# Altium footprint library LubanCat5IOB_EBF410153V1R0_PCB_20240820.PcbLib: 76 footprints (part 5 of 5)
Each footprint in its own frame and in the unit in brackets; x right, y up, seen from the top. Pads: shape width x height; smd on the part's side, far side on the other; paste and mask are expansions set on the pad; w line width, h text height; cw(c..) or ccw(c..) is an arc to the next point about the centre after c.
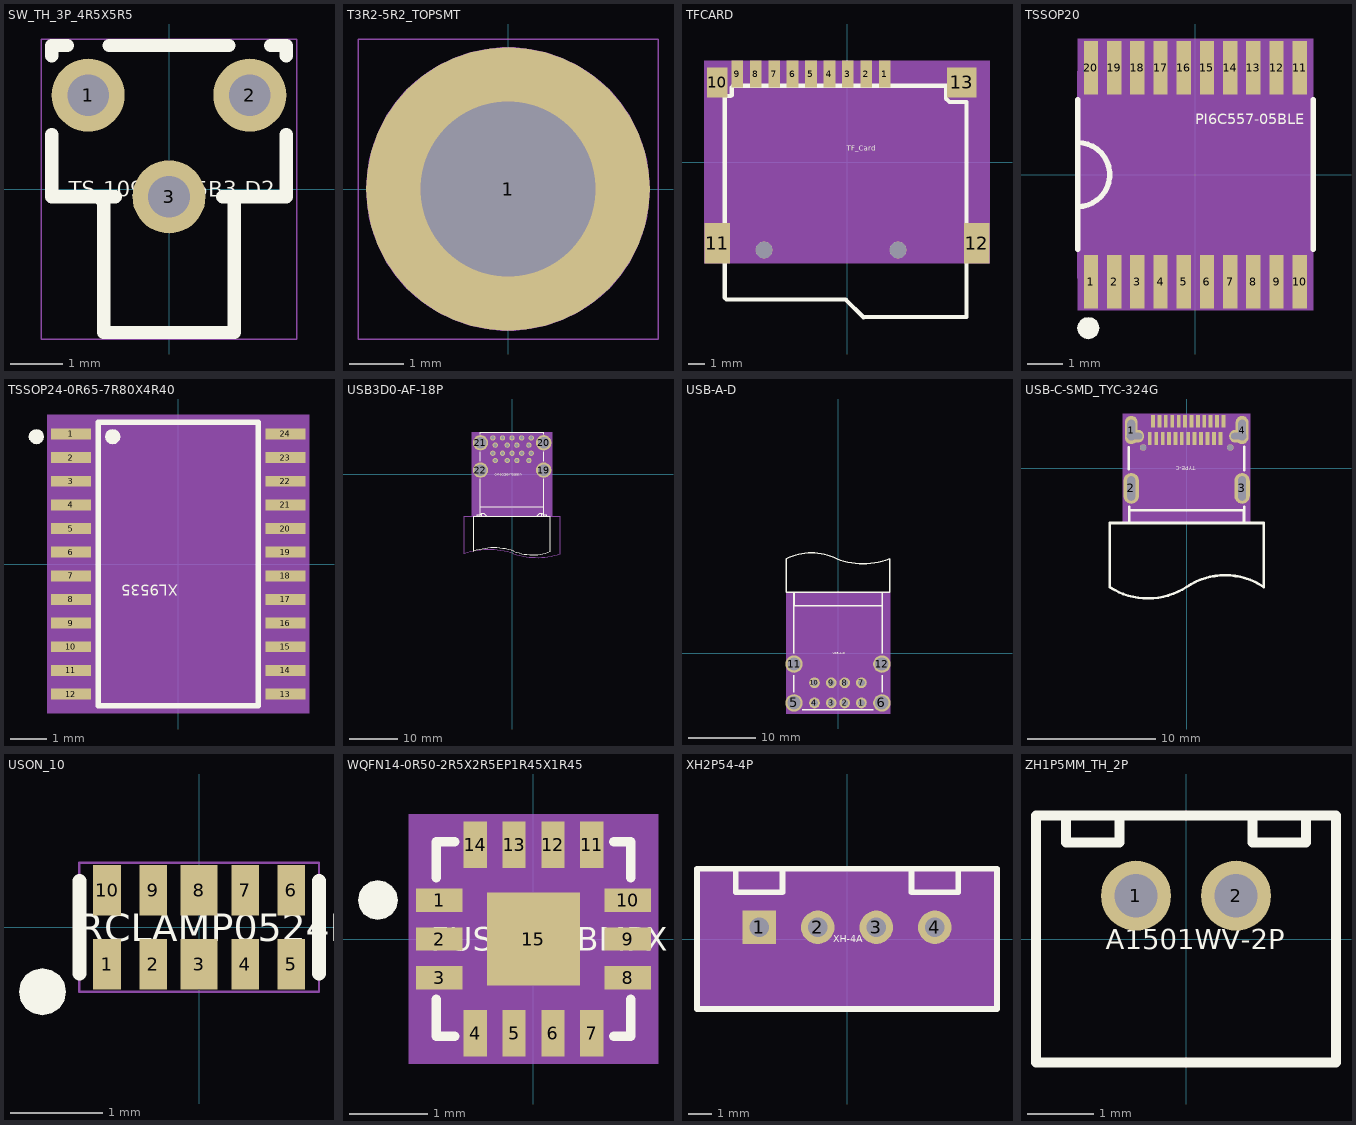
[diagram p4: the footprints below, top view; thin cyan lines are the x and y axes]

## SW_TH_3P_4R5X5R5 [mm] "SW_TH_3P_4R5X5R5"
pads (3):
  round 1.4 hole 0.8: 1(-1.55,1.8) 3(0,-0.15)
  round 1.4 / inner round 1.524 / far side round 1.4 hole 0.8: 2(1.55,1.8)
Top Overlay:
  lines w0.254: -2.25,1.044 -2.25,-0.15 -1.031,-0.15 ; -2.25,2.556 -2.25,2.75 -1.947,2.75 ; -1.359,-0.15 -1.25,-0.259 -1.25,-2.75 1.25,-2.75 1.25,-0.15 ; -1.153,2.75 1.153,2.75 ; 1.031,-0.15 2.25,-0.15 2.25,1.044 ; 1.947,2.75 2.25,2.75 2.25,2.556
  text "TS-1091B-A5B3-D2" at -1.92,-0.15 h0.3
Top 3D Body:
  lines w0.025: -2.452,-2.877 2.452,-2.877 2.452,2.877 -2.452,2.877 -2.452,-2.877
Mechanical 15:
  text "2" at 1.296,1.8 h0.64
  text "1" at -1.804,1.8 h0.64
  text "3" at -0.254,-0.15 h0.64

## T3R2-5R2_TOPSMT [mm] "T3R2-5R2_TOPSMT"
pads (1):
  round 5.2 hole 3.2: 1(0,0)
Top Overlay:
  text "M2X3mm" at -0.72,-0.15 h0.3
Top Paste:
  dashed: -2.568,0.406 -2.523,0.629 -2.458,0.846 -2.375,1.057 -2.274,1.26 -2.156,1.454 -2.021,1.636 -1.87,1.806 -1.706,1.962 -1.528,2.103 -1.339,2.228 -1.14,2.337 -0.932,2.427 -0.717,2.499 -0.496,2.552 -0.406,2.568 -0.406,1.548 -0.54,1.506 -0.669,1.454 -0.793,1.39 -0.911,1.315 -1.022,1.231 -1.126,1.137 -1.221,1.035 -1.306,0.924 -1.382,0.807 -1.447,0.684 -1.501,0.555 -1.544,0.422 -1.548,0.406
  dashed: -0.406,-2.568 -0.629,-2.523 -0.846,-2.458 -1.057,-2.375 -1.26,-2.274 -1.454,-2.156 -1.636,-2.021 -1.806,-1.87 -1.962,-1.706 -2.103,-1.528 -2.228,-1.339 -2.337,-1.14 -2.427,-0.932 -2.499,-0.717 -2.552,-0.496 -2.568,-0.406 -1.548,-0.406 -1.506,-0.54 -1.454,-0.669 -1.39,-0.793 -1.315,-0.911 -1.231,-1.022 -1.137,-1.126 -1.035,-1.221 -0.924,-1.306 -0.807,-1.382 -0.684,-1.447 -0.555,-1.501 -0.422,-1.544 -0.406,-1.548
  dashed: 2.568,-0.406 2.523,-0.629 2.458,-0.846 2.375,-1.057 2.274,-1.26 2.156,-1.454 2.021,-1.636 1.87,-1.806 1.706,-1.962 1.528,-2.103 1.339,-2.228 1.14,-2.337 0.932,-2.427 0.717,-2.499 0.496,-2.552 0.406,-2.568 0.406,-1.548 0.54,-1.506 0.669,-1.454 0.793,-1.39 0.911,-1.315 1.022,-1.231 1.126,-1.137 1.221,-1.035 1.306,-0.924 1.382,-0.807 1.447,-0.684 1.501,-0.555 1.544,-0.422 1.548,-0.406
  dashed: 0.406,2.568 0.629,2.523 0.846,2.458 1.057,2.375 1.26,2.274 1.454,2.156 1.636,2.021 1.806,1.87 1.962,1.706 2.103,1.528 2.228,1.339 2.337,1.14 2.427,0.932 2.499,0.717 2.552,0.496 2.568,0.406 1.548,0.406 1.506,0.54 1.454,0.669 1.39,0.793 1.315,0.911 1.231,1.022 1.137,1.126 1.035,1.221 0.924,1.306 0.807,1.382 0.684,1.447 0.555,1.501 0.422,1.544 0.406,1.548
Top 3D Body:
  lines w0.025: -2.75,-2.75 2.75,-2.75 2.75,2.75 -2.75,2.75 -2.75,-2.75
Mechanical 15:
  text "1" at -0.122,0 h0.3
Top Assembly:
  circle w0.025: c0,0 r2.591

## TFCARD [mil] "TFCARD"
pads (15):
  rect 27.56x62.99 smd: 1(88.58,206.82) 2(45.27,206.82) 3(1.97,206.82) 4(-41.34,206.82) 5(-84.65,206.82) 6(-127.95,206.82) 7(-171.26,206.82) 8(-214.57,206.82) 9(-257.88,206.82)
  rect 47.24x70 smd: 10(-305.12,187.13)
  rect 60x95 smd: 11(-305.12,-190.82) 12(305.12,-190.82)
  rect 70x70 smd: 13(269.68,187.13)
  round 39.37 hole 39.37 unplated: ""(-194.88,-206.57) ""(120.08,-206.57)
Top Overlay:
  lines w10: -289.12,155.18 -287.12,153.18 -287.12,-318.82 -283.12,-322.82 -3.12,-322.82 38.88,-364.82 280.88,-364.05 280.88,141.18 240.88,141.18 232.88,149.18 232.88,179.18 -267.12,179.18 -271.12,175.18 -271.12,157.18 -273.12,155.18 -289.12,155.18
  text "TF_Card" at -0.01,27.17 h11.81
Top 3D Body:
  region: -335.12,-238.31 335.12,-238.31 335.12,238.31 -335.12,238.31
Mechanical 15:
  text "12" at 305.12,-166.82 h30
  text "11" at -305.12,-166.82 h30
  text "6" at -127.95,218.82 h30
  text "13" at 269.68,211.13 h30
  text "10" at -305.12,211.13 h30
  text "4" at -41.34,218.82 h30
  text "7" at -171.26,218.82 h30
  text "3" at 1.97,218.82 h30
  text "9" at -257.88,218.82 h30
  text "5" at -84.65,218.82 h30
  text "8" at -214.57,218.82 h30
  text "2" at 45.27,218.82 h30
  text "1" at 88.58,218.82 h30
3D body: height 150, standoff 0, extent -335.12,-238.31 335.12,238.31

## TSSOP20 [mm] "TSSOP20"
pads (20):
  rect 0.4x1.5 smd: 1(-2.925,-3) 2(-2.275,-3) 3(-1.625,-3) 4(-0.975,-3) 5(-0.325,-3) 6(0.325,-3) 7(0.975,-3) 8(1.625,-3) 9(2.275,-3) 10(2.925,-3) 11(2.925,3) 12(2.275,3) 13(1.625,3) 14(0.975,3) 15(0.325,3) 16(-0.325,3) 17(-0.975,3) 18(-1.625,3) 19(-2.275,3) 20(-2.925,3)
Top Overlay:
  dashed: -3,-4.606 -2.883,-4.583 -2.784,-4.516 -2.717,-4.417 -2.694,-4.3 -2.717,-4.183 -2.74,-4.15 -2.784,-4.084 -2.883,-4.017 -3,-3.994 -3.117,-4.017 -3.216,-4.084 -3.26,-4.15 -3.283,-4.183 -3.306,-4.3 -3.283,-4.417 -3.216,-4.516 -3.117,-4.583
  lines w0.15: -3.3,-2.1 -3.3,2.1 ; -3.3,-0.9 ccw(c-3.3,0) -3.3,0.9 ; 3.3,-2.1 3.3,2.1
  text "PI6C557-05BLE" at 0,1.41 h0.3
Top 3D Body:
  region: -3.3,-3.8 3.3,-3.8 3.3,3.8 -3.3,3.8
Mechanical 15:
  text "1" at -2.925,-2.797 h0.51
  text "16" at -0.325,3.406 h0.51
  text "9" at 2.275,-2.797 h0.51
  text "11" at 2.925,3.406 h0.51
  text "12" at 2.275,3.406 h0.51
  text "13" at 1.625,3.406 h0.51
  text "14" at 0.975,3.406 h0.51
  text "15" at 0.325,3.406 h0.51
  text "19" at -2.275,3.406 h0.51
  text "17" at -0.975,3.406 h0.51
  text "20" at -2.925,3.406 h0.51
  text "18" at -1.625,3.406 h0.51
  text "6" at 0.325,-2.797 h0.51
  text "4" at -0.975,-2.797 h0.51
  text "2" at -2.275,-2.797 h0.51
  text "8" at 1.625,-2.797 h0.51
  text "5" at -0.325,-2.797 h0.51
  text "3" at -1.625,-2.797 h0.51
  text "10" at 2.925,-2.594 h0.51
  text "7" at 0.975,-2.797 h0.51
Top Assembly:
  lines w0.025: -3.3,-2.9 3.3,-2.9 3.3,2.9 -3.3,2.9 -3.3,-2.9
3D body: height 3.81, standoff 0, extent -3.3,-3.8 3.3,3.8

## TSSOP24-0R65-7R80X4R40 [mm] "TSSOP24-0R65-7R80X4R40"
pads (24):
  rect 1.1x0.3 smd: 1(-2.95,3.575) 2(-2.95,2.925) 3(-2.95,2.275) 4(-2.95,1.625) 5(-2.95,0.975) 6(-2.95,0.325) 7(-2.95,-0.325) 8(-2.95,-0.975) 9(-2.95,-1.625) 10(-2.95,-2.275) 11(-2.95,-2.925) 12(-2.95,-3.575) 13(2.95,-3.575) 14(2.95,-2.925) 15(2.95,-2.275) 16(2.95,-1.625) 17(2.95,-0.975) 18(2.95,-0.325) 19(2.95,0.325) 20(2.95,0.975) 21(2.95,1.625) 22(2.95,2.275) 23(2.95,2.925) 24(2.95,3.575)
Top Overlay:
  dashed: -3.9,3.704 -3.978,3.688 -4.044,3.644 -4.088,3.578 -4.104,3.5 -4.088,3.422 -4.074,3.4 -4.044,3.356 -3.978,3.312 -3.9,3.296 -3.822,3.312 -3.756,3.356 -3.726,3.4 -3.712,3.422 -3.696,3.5 -3.712,3.578 -3.756,3.644 -3.822,3.688
  dashed: -1.8,3.704 -1.878,3.688 -1.944,3.644 -1.988,3.578 -2.004,3.5 -1.988,3.422 -1.974,3.4 -1.944,3.356 -1.878,3.312 -1.8,3.296 -1.722,3.312 -1.656,3.356 -1.626,3.4 -1.612,3.422 -1.596,3.5 -1.612,3.578 -1.656,3.644 -1.722,3.688
  lines w0.15: -2.2,-3.9 -2.2,3.9 2.2,3.9 2.2,-3.9 -2.2,-3.9
  text "XL9535" at 0,-0.57 h0.3
Top 3D Body:
  region: -3.6,4.1 -3.6,-4.1 3.6,-4.1 3.6,4.1
Mechanical 15:
  text "21" at 2.95,1.325 h0.25
  text "24" at 2.95,3.275 h0.25
  text "12" at -2.95,-3.875 h0.25
  text "3" at -2.95,2.075 h0.25
  text "2" at -2.95,2.725 h0.25
  text "23" at 2.95,2.625 h0.25
  text "22" at 2.95,1.975 h0.25
  text "19" at 2.95,0.025 h0.25
  text "20" at 2.95,0.675 h0.25
  text "17" at 2.95,-1.275 h0.25
  text "18" at 2.95,-0.625 h0.25
  text "16" at 2.95,-1.925 h0.25
  text "15" at 2.95,-2.575 h0.25
  text "14" at 2.95,-3.225 h0.25
  text "13" at 2.95,-3.875 h0.25
  text "11" at -2.95,-3.225 h0.25
  text "10" at -2.95,-2.575 h0.25
  text "9" at -2.95,-1.825 h0.25
  text "8" at -2.95,-1.175 h0.25
  text "7" at -2.95,-0.525 h0.25
  text "6" at -2.95,0.125 h0.25
  text "5" at -2.95,0.775 h0.25
  text "4" at -2.95,1.425 h0.25
  text "1" at -2.95,3.375 h0.25
Top Assembly:
  lines w0.15: -3.2,-3.9 -3.2,3.9 3.2,3.9 3.2,-3.9 -3.2,-3.9
3D body: height 3.81, standoff 0, extent -3.6,-4.1 3.6,4.1

## USB3D0-AF-18P [mm] "USB3D0-AF-18P"
pads (22):
  round 1.1 / inner round 1.524 / far side round 1.1 hole 0.7: 1(-3.5,2.899) 2(-1.001,2.899) 3(1.001,2.899) 5(4,4.401) 6(1.999,4.401) 8(-1.999,4.401) 9(-4,4.401) 10(-3.5,6.1) 11(-1.001,6.1) 12(1.001,6.1) 14(4,7.601) 15(1.999,7.601) 17(-1.999,7.601) 18(-4,7.601)
  round 1.1 hole 0.7: 4(3.5,2.899) 7(0,4.401) 13(3.5,6.1) 16(0,7.601)
  round 3.2 / inner round 1.524 / far side round 3.2 hole 2.4: 19(6.571,0.9) 20(6.571,6.58) 21(-6.571,6.58) 22(-6.571,0.9)
Top Overlay:
  lines w0.15: -7.257,-8.719 -6.284,-8.719 -6.284,-8.091 -5.86,-8.091 -5.235,-8.719 5.067,-8.719 ; -7.257,-8.388 -6.617,-8.388 -6.284,-8.056 ; -6.571,-0.931 -6.571,-3.299 -6.571,-4.379 -6.571,-8.719 -6.571,-6.719 6.571,-6.719 6.571,-8.719 6.571,-4.879 6.571,-3.999 6.571,-0.931 ; -6.571,2.732 -6.571,4.749 ; -6.571,8.411 -6.571,8.774 6.571,8.774 6.571,8.411 ; 5.169,-8.719 5.796,-8.091 6.218,-8.091 6.218,-8.719 7.193,-8.719 ; 6.218,-8.056 6.551,-8.388 7.193,-8.388 ; 6.571,2.732 6.571,4.749 ; -8,-16.019 cw(c-3.773,-28.033) 0.4,-15.999 ccw(c4.224,-6.389) 8,-16.019 8,-8.719 0,-8.719 -8,-8.719 -8,-16.019
  lines w0.254: -7.257,-8.719 -7.257,-8.388 ; 7.193,-8.719 7.193,-8.388
  text "USB3D0_USB2D0-A-D" at 2.04,0.15 h0.3
Bottom Overlay:
  drawing of 19 lines, arcs and shapes, not listed
Top 3D Body:
  region: -8.4,8.8 -8.4,-8.8 8.4,-8.8 8.4,8.8
Mechanical 15:
  text "11" at -0.493,6.1 h0.64
  text "3" at 1.255,2.899 h0.64
  text "9" at -3.746,4.401 h0.64
  text "7" at 0.254,4.401 h0.64
  text "4" at 3.754,2.899 h0.64
  text "16" at 0.508,7.601 h0.64
  text "13" at 4.008,6.1 h0.64
  text "8" at -1.745,4.401 h0.64
  text "19" at 7.079,0.9 h0.64
  text "20" at 7.079,6.58 h0.64
  text "21" at -6.063,6.58 h0.64
  text "22" at -6.063,0.9 h0.64
  text "1" at -3.246,2.899 h0.64
  text "6" at 2.253,4.401 h0.64
  text "10" at -2.992,6.1 h0.64
  text "5" at 4.255,4.401 h0.64
  text "12" at 1.509,6.1 h0.64
  text "2" at -0.747,2.899 h0.64
  text "18" at -3.492,7.601 h0.64
  text "17" at -1.491,7.601 h0.64
  text "15" at 2.507,7.601 h0.64
  text "14" at 4.508,7.601 h0.64
Top Assembly:
  lines w0.15: -10,-16.519 cw(c-4.77,-32.788) 0.4,-16.499 ccw(c5.228,-2.363) 10,-16.519 10,-8.719 0,-8.719 -10,-8.719 -10,-16.519
3D body: height 3.81, standoff 0, extent -8.4,-8.8 8.4,8.8

## USB-A-D [mm] "USB-A-D"
pads (12):
  round 1.6 / inner round 1.524 / far side round 1.6 hole 1: 1(3.45,-7.425) 2(0.95,-7.425) 3(-1.05,-7.425) 7(3.45,-4.425) 8(0.95,-4.425) 9(-1.05,-4.425)
  round 1.6 hole 1: 4(-3.55,-7.425) 10(-3.55,-4.425)
  round 2.6 / inner round 1.524 / far side round 2.6 hole 2: 5(-6.6,-7.425) 6(6.5,-7.425) 11(-6.6,-1.625) 12(6.5,-1.625)
Top Overlay:
  lines w0.2: -6.65,-5.825 -6.65,-3.325 ; -6.65,-0.025 -6.65,9.075 6.55,9.075 ; -6.6,9.075 -6.6,7.075 6.55,7.075 6.55,9.075 ; -5.35,-8.425 5.25,-8.425 ; 6.55,-5.825 6.55,-3.325 ; 6.55,-0.025 6.55,9.075 ; -7.75,9.075 -7.75,14.075 cw(c-4,6.725) -0.25,14.075 ccw(c3.7,24.508) 7.65,14.075 7.65,9.075 -7.75,9.075
  text "USB-A-D" at -0.84,-0.15 h0.3
Bottom Overlay:
  drawing of 9 lines, arcs and shapes, not listed
Top 3D Body:
  region: -7.75,-9.075 7.75,-9.075 7.75,9.075 -7.75,9.075
Mechanical 15:
  text "2" at 0.696,-7.425 h0.64
  text "4" at -3.804,-7.425 h0.64
  text "10" at -4.058,-4.425 h0.64
  text "3" at -1.304,-7.425 h0.64
  text "7" at 3.196,-4.425 h0.64
  text "1" at 3.196,-7.425 h0.64
  text "9" at -1.304,-4.425 h0.64
  text "8" at 0.696,-4.425 h0.64
  text "11" at -7.108,-1.625 h0.64
  text "5" at -6.854,-7.425 h0.64
  text "12" at 5.992,-1.625 h0.64
  text "6" at 6.246,-7.425 h0.64
Top Assembly:
  lines w0.025: -6.6,-8.425 6.5,-8.425 6.5,9.075 -6.6,9.075 -6.6,-8.425
3D body: height 3.81, standoff 0, extent -7.75,-9.075 7.75,9.075

## USB-C-SMD_TYC-324G [mm] "USB-C-SMD_TYC-324G"
pads (32):
  oval 1x2.2 / inner round 1.524 / far side oval 1x2.2 hole 1.6 slot 0.6 at 0 deg: 1(-4.32,2.99) 4(4.32,2.99)
  oval 1.2x2.4 / inner round 1.524 / far side oval 1.2x2.4 hole 1.9 slot 0.6 at 0 deg: 2(-4.32,-1.56) 3(4.32,-1.56)
  rect 0.3x1 smd: A1(-2.62,3.68) A2(-2.13,3.68) A3(-1.63,3.68) A4(-1.13,3.68) A5(-0.62,3.68) A6(-0.12,3.68) A7(0.38,3.68) A8(0.88,3.68) A9(1.37,3.68) A10(1.87,3.68) A11(2.37,3.68) A12(2.88,3.68) B1(2.63,2.34) B2(2.13,2.34) B3(1.63,2.34) B4(1.13,2.34) B5(0.62,2.34) B6(0.12,2.34) B7(-0.38,2.34) B8(-0.87,2.34) B9(-1.37,2.34) B10(-1.87,2.34) B11(-2.37,2.34) B12(-2.88,2.34)
  oval 1.5x1 hole 0.5 slot 1.2 at 0 deg: ""(-4.06,2.51) ""(4.06,2.51)
  round 0.5 hole 0.5 unplated: ""(-3.4,1.63) ""(3.4,1.63)
Top Overlay:
  lines w0.2: -4.5,-0.06 -4.5,1.65 ; -4.47,-3 -4.47,-3.26 ; 4.5,-2.98 4.5,-4.24 4.47,-4.26 ; 4.5,-0.14 4.5,1.67 ; 6,-9.26 6,-4.26 -6,-4.26 -6,-9.26 ccw(c-3.015,-4.643) 0,-9.24 cw(c3,-13.74) 6,-9.24 ; -4.47,-3.26 4.47,-3.26 4.47,-4.26 ; -4.47,-3.26 -4.47,-4.26 4.47,-4.26
  text "TYPE-C" at 0.72,0.15 h0.3
Top 3D Body:
  region: -4.97,-4.24 4.97,-4.24 4.97,4.24 -4.97,4.24
Mechanical 15:
  text "A10" at 1.99,3.68 h0.1
  text "A2" at -2.05,3.68 h0.1
  text "2" at -4.28,-1.56 h0.1
  text "1" at -4.28,2.99 h0.1
  text "3" at 4.36,-1.56 h0.1
  text "4" at 4.36,2.99 h0.1
  text "B7" at -0.3,2.34 h0.1
  text "A7" at 0.46,3.68 h0.1
  text "A8" at 0.96,3.68 h0.1
  text "A9" at 1.45,3.68 h0.1
  text "B4" at 1.21,2.34 h0.1
  text "A4" at -1.05,3.68 h0.1
  text "B9" at -1.29,2.34 h0.1
  text "B1" at 2.71,2.34 h0.1
  text "A12" at 3,3.68 h0.1
  text "A1" at -2.54,3.68 h0.1
  text "B12" at -2.76,2.34 h0.1
  text "B8" at -0.79,2.34 h0.1
  text "A11" at 2.49,3.68 h0.1
  text "B2" at 2.21,2.34 h0.1
  text "A3" at -1.55,3.68 h0.1
  text "A5" at -0.54,3.68 h0.1
  text "B5" at 0.7,2.34 h0.1
  text "B6" at 0.2,2.34 h0.1
  text "A6" at -0.04,3.68 h0.1
  text "B11" at -2.25,2.34 h0.1
  text "B10" at -1.75,2.34 h0.1
  text "B3" at 1.71,2.34 h0.1
3D body: height 3.81, standoff 0, extent -4.97,-4.24 4.97,4.24

## USON_10 [mm] "USON_10"
pads (10):
  rect 0.3x0.55 smd: 1(-1,-0.4) 2(-0.5,-0.4) 4(0.5,-0.4) 5(1,-0.4) 6(1,0.4) 7(0.5,0.4) 9(-0.5,0.4) 10(-1,0.4)
  rect 0.4x0.55 smd: 3(0,-0.4) 8(0,0.4)
Top Overlay:
  dashed: -1.445,-0.7 -1.465,-0.602 -1.52,-0.52 -1.602,-0.465 -1.7,-0.445 -1.798,-0.465 -1.825,-0.483 -1.88,-0.52 -1.935,-0.602 -1.955,-0.7 -1.935,-0.798 -1.88,-0.88 -1.825,-0.917 -1.798,-0.935 -1.7,-0.955 -1.602,-0.935 -1.52,-0.88 -1.465,-0.798
  lines w0.15: -1.3,-0.5 -1.3,0.5 ; 1.3,-0.5 1.3,0.5
  text "RCLAMP0524P" at -1.32,-0.15 h0.3
Top 3D Body:
  lines w0.025: -1.3,-0.7 1.3,-0.7 1.3,0.7 -1.3,0.7 -1.3,-0.7
Mechanical 15:
  text "9" at -0.754,0.4 h0.64
  text "2" at -0.754,-0.4 h0.64
  text "3" at -0.254,-0.4 h0.64
  text "8" at -0.254,0.4 h0.64
  text "10" at -1.508,0.4 h0.64
  text "1" at -1.254,-0.4 h0.64
  text "7" at 0.246,0.4 h0.64
  text "4" at 0.246,-0.4 h0.64
  text "6" at 0.746,0.4 h0.64
  text "5" at 0.746,-0.4 h0.64

## WQFN14-0R50-2R5X2R5EP1R45X1R45 [mm] "WQFN14-0R50-2R5X2R5EP1R45X1R45"
pads (15):
  rect 0.6x0.3 smd: 1(-1.21,0.5) 2(-1.21,0) 3(-1.21,-0.5) 8(1.21,-0.5) 9(1.21,0) 10(1.21,0.5)
  rect 0.3x0.6 smd: 4(-0.75,-1.21) 5(-0.25,-1.21) 6(0.25,-1.21) 7(0.75,-1.21) 11(0.75,1.21) 12(0.25,1.21) 13(-0.25,1.21) 14(-0.75,1.21)
  rect 1.2x1.2 smd: 15(0,0)
Top Overlay:
  dashed: -1.745,0.5 -1.765,0.598 -1.82,0.68 -1.902,0.735 -2,0.755 -2.098,0.735 -2.125,0.717 -2.18,0.68 -2.235,0.598 -2.255,0.5 -2.235,0.402 -2.18,0.32 -2.125,0.283 -2.098,0.265 -2,0.245 -1.902,0.265 -1.82,0.32 -1.765,0.402
  lines w0.127: -1.25,-0.777 -1.25,-1.25 -1.016,-1.25 ; -1.25,0.789 -1.25,1.25 -1.016,1.25 ; 1.034,-1.25 1.25,-1.25 1.25,-0.777 ; 1.034,1.25 1.25,1.25 1.25,0.789
  text "FUSB302BMPX" at -1.32,-0.15 h0.3
Top 3D Body:
  region: -1.6,1.6 -1.6,-1.6 1.6,-1.6 1.6,1.6
Mechanical 15:
  text "4" at -0.79,-1.21 h0.1
  text "3" at -1.25,-0.5 h0.1
  text "2" at -1.25,0 h0.1
  text "9" at 1.17,0 h0.1
  text "15" at -0.08,0 h0.1
  text "8" at 1.17,-0.5 h0.1
  text "6" at 0.21,-1.21 h0.1
  text "12" at 0.17,1.21 h0.1
  text "13" at -0.33,1.21 h0.1
  text "7" at 0.71,-1.21 h0.1
  text "11" at 0.67,1.21 h0.1
  text "10" at 1.13,0.5 h0.1
  text "14" at -0.83,1.21 h0.1
  text "1" at -1.25,0.5 h0.1
  text "5" at -0.29,-1.21 h0.1
Top Assembly:
  lines w0.025: -1.51,-1.36 1.51,-1.36 1.51,1.36 -1.51,1.36 -1.51,-1.36
3D body: height 3.81, standoff 0, extent -1.6,-1.6 1.6,1.6

## XH2P54-4P [mm] "XH2P54-4P"
pads (4):
  rect 1.45x1.45 / inner round 1.524 / far side rect 1.45x1.45 hole 0.85: 1(-3.81,0.508)
  round 1.45 hole 0.85: 2(-1.27,0.508) 3(1.27,0.508)
  round 1.45 / inner round 1.524 / far side round 1.45 hole 0.85: 4(3.81,0.508)
Top Overlay:
  lines w0.254: -6.51,-3.032 -6.51,3.048 6.51,3.048 6.51,-3.032 -6.51,-3.032 ; -4.826,2.032 -4.826,3.048 -2.794,3.048 -2.794,2.032 -4.826,2.032 ; 2.794,2.032 2.794,3.048 4.826,3.048 4.826,2.032 2.794,2.032
  text "XH-4A" at -0.6,-0.15 h0.3
Bottom Overlay:
  lines w0.6: -2.54,-0.092 -2.54,1.108 ; 0,-0.092 0,1.108 ; 2.54,-0.092 2.54,1.108
Top 3D Body:
  region: -6.477,-3.048 6.477,-3.048 6.477,3.048 -6.477,3.048
Mechanical 15:
  text "2" at -1.524,0.508 h0.64
  text "3" at 1.016,0.508 h0.64
  text "1" at -4.064,0.508 h0.64
  text "4" at 3.556,0.508 h0.64
Top Assembly:
  lines w0.025: -6.477,-3.048 6.51,-3.048 6.51,3.048 -6.477,3.048 -6.477,-3.048
3D body: height 3.81, standoff 0, extent -6.477,-3.048 6.477,3.048

## ZH1P5MM_TH_2P [mm] "ZH1P5MM_TH_2P"
pads (2):
  round 1.05 / inner round 1.524 / far side round 1.05 hole 0.65: 1(-0.75,0.65)
  round 1.05 hole 0.65: 2(0.75,0.65)
Top Overlay:
  lines w0.15: -1.8,1.85 -1.8,1.45 -1,1.45 -1,1.85 ; 1,1.85 1,1.45 1.8,1.45 1.8,1.85 ; -2.25,-1.85 2.25,-1.85 2.25,1.85 -2.25,1.85 -2.25,-1.85
  text "A1501WV-2P" at -1.2,-0.15 h0.3
Bottom Overlay:
  lines w0.3: 0,-0.15 0,1.45 ; -1.5,-0.15 -1.5,1.45 1.5,1.45 1.5,-0.15 -1.3,-0.15 -1.5,-0.15
Top 3D Body:
  lines w0.025: -2.2,-1.85 2.2,-1.85 2.2,1.85 -2.2,1.85 -2.2,-1.85
Mechanical 15:
  text "2" at 0.435,0.65 h0.79
  text "1" at -1.065,0.65 h0.79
